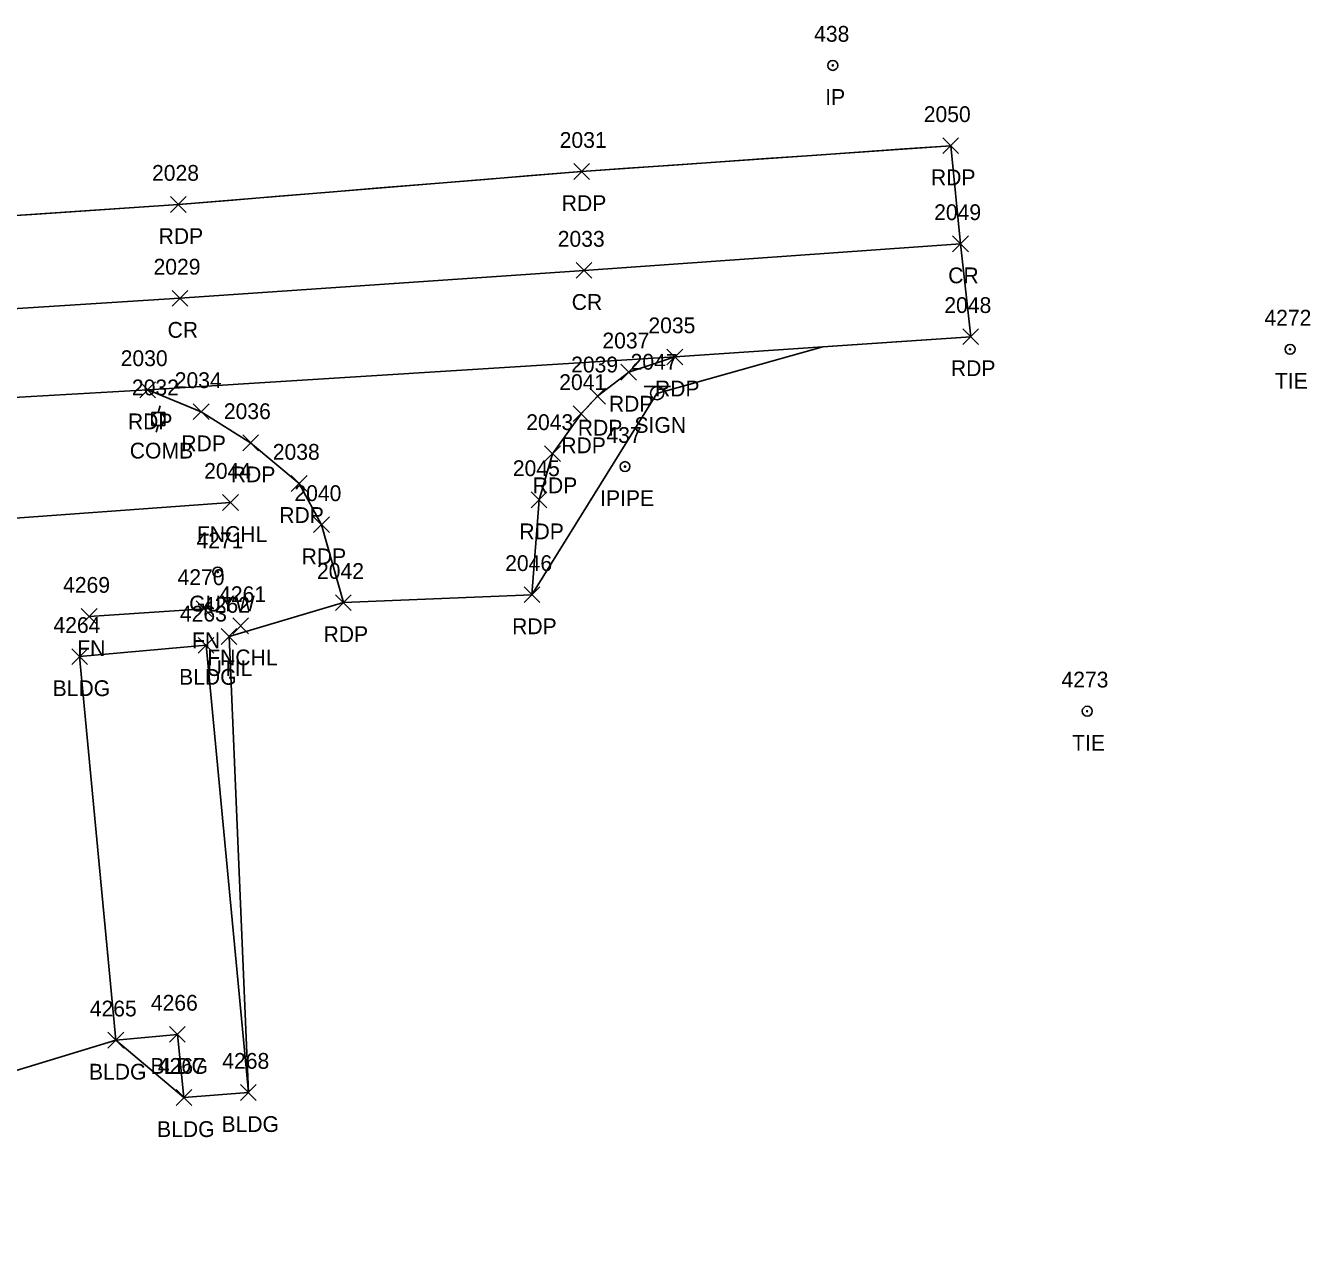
# Model space of a CAD drawing. Extents: x 1509053 to 1511576, y 400838 to 402572.
# Drawn here: x 1510951.8 to 1511114.5, y 401558.4 to 401712.6 of the extents above; entities that cross this region are included whole.
import ezdxf

# ---------------------------------------------------------------- set-up
doc = ezdxf.new("R2010")
doc.units = 0
for name, color, linetype in [('C_A', 7, 'Continuous'), ('C_I', 7, 'Continuous'), ('CBP', 7, 'Continuous'), ('L_A', 7, 'Continuous'), ('L_I', 7, 'Continuous'), ('L_TIC', 7, 'Continuous'), ('LBC', 7, 'Continuous'), ('LFNC', 7, 'Continuous'), ('LSOGP', 7, 'Continuous'), ('M_A', 7, 'Continuous'), ('M_I', 7, 'Continuous'), ('MPIP', 7, 'Continuous'), ('MPIR', 7, 'Continuous'), ('P_A', 7, 'Continuous'), ('P_I', 7, 'Continuous'), ('P_TIC', 7, 'Continuous'), ('PET', 7, 'Continuous'), ('PRC', 7, 'Continuous'), ('S_A', 7, 'Continuous'), ('S_I', 7, 'Continuous'), ('SSGN', 7, 'Continuous'), ('U_A', 7, 'Continuous'), ('U_I', 7, 'Continuous'), ('UDEFAULT', 7, 'Continuous'), ('UP', 7, 'Continuous'), ('UPGW', 7, 'Continuous')]:
    doc.layers.add(name, color=color, linetype=linetype)

msp = doc.modelspace()

# ---------------------------------------------------------------- linework, layer by layer
at = {"layer": 'CBP'}
for centre, radius in [((1511111.96, 401671.62), 0.625), ((1511111.96, 401671.62), 0.0833), ((1511086.25, 401625.79), 0.625), ((1511086.25, 401625.79), 0.0833)]:
    msp.add_circle(centre, radius, dxfattribs=at)
at = {"layer": 'L_TIC'}
for points in [[(1510976.71, 401651.22), (1510978.71, 401653.22)], [(1510978.71, 401651.22), (1510976.71, 401653.22)], [(1510973.36, 401637.76), (1510975.36, 401639.76)], [(1510975.36, 401637.76), (1510973.36, 401639.76)], [(1510958.81, 401636.78), (1510960.81, 401638.78)], [(1510960.81, 401636.78), (1510958.81, 401638.78)], [(1510978.01, 401635.6), (1510980.01, 401637.6)], [(1510980.01, 401635.6), (1510978.01, 401637.6)], [(1510973.61, 401633.14), (1510975.61, 401635.14)], [(1510975.61, 401633.14), (1510973.61, 401635.14)], [(1510957.59, 401631.7), (1510959.59, 401633.7)], [(1510959.59, 401631.7), (1510957.59, 401633.7)], [(1510969.98, 401583.86), (1510971.98, 401585.86)], [(1510971.98, 401583.86), (1510969.98, 401585.86)], [(1510962.19, 401583.13), (1510964.19, 401585.13)], [(1510964.19, 401583.13), (1510962.19, 401585.13)], [(1510970.82, 401575.86), (1510972.82, 401577.86)], [(1510972.82, 401575.86), (1510970.82, 401577.86)], [(1510978.98, 401576.5), (1510980.98, 401578.5)], [(1510980.98, 401576.5), (1510978.98, 401578.5)]]:
    msp.add_lwpolyline(points, dxfattribs=at)
at = {"layer": 'LBC'}
for points in [[(1510974.61, 401634.14), (1510958.59, 401632.7), (1510963.19, 401584.13), (1510970.98, 401584.86), (1510971.82, 401576.86), (1510979.98, 401577.5)], [(1510979.98, 401577.5), (1510974.61, 401634.14)]]:
    msp.add_lwpolyline(points, dxfattribs=at)
at = {"layer": 'LFNC'}
for points in [[(1510614.51, 401587.89), (1510608.95, 401624.6), (1510623.43, 401626.88), (1510653.12, 401627.01), (1510659.85, 401628.01), (1510675.67, 401629.95), (1510724.73, 401633.47), (1510773.82, 401637.15), (1510823.89, 401641.02), (1510977.71, 401652.22)], [(1510959.81, 401637.78), (1510974.36, 401638.76)]]:
    msp.add_lwpolyline(points, dxfattribs=at)
at = {"layer": 'LSOGP'}
msp.add_lwpolyline([(1510878.7, 401558.4), (1510963.19, 401584.13), (1510971.82, 401576.86), (1510979.98, 401577.5), (1510977.53, 401635.25), (1510992.01, 401639.54), (1511015.9, 401640.54), (1511031.74, 401666.04), (1511052.74, 401671.93), (1511062.11, 401672.57), (1511071.49, 401673.22), (1511070.2, 401684.98), (1511068.96, 401697.4), (1511063.11, 401696.99), (1511057.27, 401696.58), (1511051.42, 401696.17), (1511045.58, 401695.77), (1511039.73, 401695.36), (1511033.88, 401694.95), (1511028.04, 401694.54), (1511022.19, 401694.13), (1511015.81, 401693.61), (1511009.42, 401693.09), (1511003.03, 401692.57), (1510996.65, 401692.05), (1510990.26, 401691.52), (1510983.88, 401691), (1510977.49, 401690.48), (1510971.11, 401689.96), (1510964.93, 401689.55), (1510958.75, 401689.13), (1510952.56, 401688.71), (1510946.38, 401688.3)], dxfattribs=at)
at = {"layer": 'MPIP'}
for radius in [0.625, 0.0833]:
    msp.add_circle((1511027.7, 401656.77), radius, dxfattribs=at)
at = {"layer": 'MPIR'}
for radius in [0.625, 0.0833]:
    msp.add_circle((1511054.02, 401707.57), radius, dxfattribs=at)
at = {"layer": 'P_TIC'}
for points in [[(1511067.96, 401696.4), (1511069.96, 401698.4)], [(1511069.96, 401696.4), (1511067.96, 401698.4)], [(1511021.19, 401693.13), (1511023.19, 401695.13)], [(1511023.19, 401693.13), (1511021.19, 401695.13)], [(1510970.11, 401688.96), (1510972.11, 401690.96)], [(1510972.11, 401688.96), (1510970.11, 401690.96)], [(1511069.2, 401683.98), (1511071.2, 401685.98)], [(1511071.2, 401683.98), (1511069.2, 401685.98)], [(1511021.51, 401680.61), (1511023.51, 401682.61)], [(1511023.51, 401680.61), (1511021.51, 401682.61)], [(1510970.31, 401677.08), (1510972.31, 401679.08)], [(1510972.31, 401677.08), (1510970.31, 401679.08)], [(1511070.49, 401672.21), (1511072.49, 401674.21)], [(1511072.49, 401672.21), (1511070.49, 401674.21)], [(1511033, 401669.65), (1511035, 401671.65)], [(1511035, 401669.65), (1511033, 401671.65)], [(1511033, 401669.65), (1511035, 401671.65)], [(1511035, 401669.65), (1511033, 401671.65)], [(1511027.17, 401667.73), (1511029.17, 401669.73)], [(1511029.17, 401667.73), (1511027.17, 401669.73)], [(1510966.23, 401665.49), (1510968.23, 401667.49)], [(1510968.23, 401665.49), (1510966.23, 401667.49)], [(1510966.23, 401665.49), (1510968.23, 401667.49)], [(1510968.23, 401665.49), (1510966.23, 401667.49)], [(1511023.22, 401664.69), (1511025.22, 401666.69)], [(1511025.22, 401664.69), (1511023.22, 401666.69)], [(1510972.99, 401662.71), (1510974.99, 401664.71)], [(1510974.99, 401662.71), (1510972.99, 401664.71)], [(1511021.14, 401662.46), (1511023.13, 401664.46)], [(1511023.13, 401662.46), (1511021.14, 401664.46)], [(1510979.26, 401658.78), (1510981.26, 401660.78)], [(1510981.26, 401658.78), (1510979.26, 401660.78)], [(1511017.51, 401657.39), (1511019.51, 401659.39)], [(1511019.51, 401657.39), (1511017.51, 401659.39)], [(1510985.41, 401653.63), (1510987.41, 401655.63)], [(1510987.41, 401653.63), (1510985.41, 401655.63)], [(1511015.81, 401651.56), (1511017.81, 401653.56)], [(1511017.81, 401651.56), (1511015.81, 401653.56)], [(1510988.24, 401648.4), (1510990.24, 401650.4)], [(1510990.24, 401648.4), (1510988.24, 401650.4)], [(1511014.9, 401639.54), (1511016.9, 401641.54)], [(1511016.9, 401639.54), (1511014.9, 401641.54)], [(1510991.01, 401638.54), (1510993.01, 401640.54)], [(1510993.01, 401638.54), (1510991.01, 401640.54)]]:
    msp.add_lwpolyline(points, dxfattribs=at)
at = {"layer": 'PET'}
for points in [[(1510621.58, 401670.53), (1510656.11, 401672.66), (1510671.73, 401673.2), (1510721.32, 401677.33), (1510730.99, 401677.85), (1510771.86, 401678.86), (1510821.69, 401680.89), (1510871.79, 401683.93), (1510921.66, 401686.63), (1510971.11, 401689.96), (1511022.19, 401694.13), (1511068.96, 401697.4)], [(1510069.7, 401647.38), (1510070.82, 401637.95), (1510072.41, 401628.04), (1510122.3, 401634.81), (1510170.19, 401640.65), (1510220.23, 401643.86), (1510269.72, 401644.29), (1510320.63, 401641.42), (1510370.24, 401637.87), (1510421.73, 401637.03), (1510472.3, 401638.25), (1510523.24, 401640.81), (1510571.7, 401643.53), (1510622.45, 401646.41), (1510672.72, 401649.13), (1510722.86, 401651.91), (1510723.41, 401651.94), (1510773.15, 401654.37), (1510822.4, 401657.74), (1510872.35, 401660.8), (1510922.85, 401663.95), (1510967.23, 401666.49), (1511034, 401670.65), (1511071.49, 401673.22)], [(1511034, 401670.65), (1511028.17, 401668.73), (1511024.22, 401665.69), (1511022.14, 401663.46), (1511018.51, 401658.39), (1511016.81, 401652.56), (1511015.9, 401640.54)], [(1510967.23, 401666.49), (1510973.99, 401663.71), (1510980.26, 401659.78), (1510986.41, 401654.63), (1510989.24, 401649.4), (1510992.01, 401639.54)]]:
    msp.add_lwpolyline(points, dxfattribs=at)
at = {"layer": 'PRC'}
msp.add_lwpolyline([(1510070.82, 401637.95), (1510120.23, 401645.42), (1510169.76, 401652.13), (1510220.07, 401655.52), (1510220.14, 401655.43), (1510270.51, 401655.53), (1510320.84, 401653.34), (1510371.03, 401650.53), (1510421.26, 401649.11), (1510471.33, 401650.1), (1510521.34, 401652.38), (1510571.58, 401655.12), (1510621.67, 401657.75), (1510671.66, 401660.66), (1510722.15, 401663.46), (1510772.15, 401666.42), (1510822.28, 401669.1), (1510872.26, 401671.98), (1510872.29, 401672.01), (1510922.21, 401674.96), (1510971.31, 401678.08), (1511022.51, 401681.61), (1511070.2, 401684.98)], dxfattribs=at)
at = {"layer": 'SSGN'}
for p, q in [((1511030.11, 401666.9), (1511033.44, 401666.9)), ((1511031.76, 401666.06), (1511031.76, 401666.06))]:
    msp.add_line(p, q, dxfattribs=at)
msp.add_circle((1511031.76, 401666.06), 0.833, dxfattribs=at)
at = {"layer": 'UDEFAULT'}
for points in [[(1510976.53, 401634.25), (1510978.53, 401636.25)], [(1510978.53, 401634.25), (1510976.53, 401636.25)]]:
    msp.add_lwpolyline(points, dxfattribs=at)
at = {"layer": 'UP'}
for p, q in [((1510967.73, 401661.96), (1510967.73, 401663.62)), ((1510967.73, 401663.62), (1510969.39, 401663.62)), ((1510968.81, 401664.46), (1510968.56, 401663.62)), ((1510969.39, 401663.62), (1510969.39, 401661.96)), ((1510969.39, 401661.96), (1510967.73, 401661.96)), ((1510968.31, 401661.12), (1510968.56, 401661.96)), ((1510968.56, 401662.79), (1510968.56, 401662.79))]:
    msp.add_line(p, q, dxfattribs=at)
msp.add_circle((1510968.56, 401662.79), 0.833, dxfattribs=at)
at = {"layer": 'UPGW'}
for radius in [0.625, 0.0833]:
    msp.add_circle((1510976.09, 401643.42), radius, dxfattribs=at)

# ---------------------------------------------------------------- texts
at = {"layer": 'C_A'}
for p in [(1511110.04, 401666.62), (1511084.33, 401620.79)]:
    msp.add_text('TIE', height=2, dxfattribs=at).set_placement(p)
at = {"layer": 'C_I'}
for s, p in [('4272', (1511108.7, 401674.62)), ('4273', (1511082.99, 401628.79))]:
    msp.add_text(s, height=2, dxfattribs=at).set_placement(p)
at = {"layer": 'L_A'}
for s, p in [('FNCHL', (1510973.45, 401647.22)), ('FN', (1510972.84, 401633.76)), ('FN', (1510958.29, 401632.78)), ('FNCHL', (1510974.76, 401631.6)), ('BLDG', (1510971.2, 401629.14)), ('BLDG', (1510955.18, 401627.7)), ('BLDG', (1510959.78, 401579.13)), ('BLDG', (1510967.57, 401579.86)), ('BLDG', (1510968.41, 401571.86)), ('BLDG', (1510976.57, 401572.5))]:
    msp.add_text(s, height=2, dxfattribs=at).set_placement(p)
at = {"layer": 'L_I'}
for s, p in [('2044', (1510974.37, 401655.22)), ('4269', (1510956.5, 401640.78)), ('4270', (1510971.01, 401641.76)), ('4261', (1510976.27, 401639.6)), ('4263', (1510971.3, 401637.14)), ('4264', (1510955.28, 401635.7)), ('4265', (1510959.88, 401587.13)), ('4266', (1510967.62, 401587.86)), ('4268', (1510976.67, 401580.5)), ('4267', (1510968.51, 401579.86))]:
    msp.add_text(s, height=2, dxfattribs=at).set_placement(p)
at = {"layer": 'M_A'}
for s, p in [('IP', (1511053.06, 401702.57)), ('IPIPE', (1511024.54, 401651.77))]:
    msp.add_text(s, height=2, dxfattribs=at).set_placement(p)
at = {"layer": 'M_I'}
for s, p in [('438', (1511051.65, 401710.57)), ('437', (1511025.34, 401659.77))]:
    msp.add_text(s, height=2, dxfattribs=at).set_placement(p)
at = {"layer": 'P_A'}
for s, p in [('RDP', (1511066.45, 401692.4)), ('RDP', (1511019.68, 401689.13)), ('RDP', (1510968.6, 401684.96)), ('CR', (1511068.64, 401679.98)), ('CR', (1511020.94, 401676.61)), ('CR', (1510969.74, 401673.08)), ('RDP', (1511068.98, 401668.22)), ('RDP', (1511031.49, 401665.65)), ('RDP', (1511031.49, 401665.65)), ('RDP', (1511025.65, 401663.73)), ('RDP', (1510964.71, 401661.49)), ('RDP', (1510964.71, 401661.49)), ('RDP', (1511021.71, 401660.69)), ('RDP', (1510971.48, 401658.71)), ('RDP', (1511019.62, 401658.46)), ('RDP', (1510977.75, 401654.78)), ('RDP', (1511016, 401653.39)), ('RDP', (1510983.89, 401649.63)), ('RDP', (1511014.3, 401647.56)), ('RDP', (1510986.72, 401644.4)), ('RDP', (1511013.39, 401635.54)), ('RDP', (1510989.5, 401634.54))]:
    msp.add_text(s, height=2, dxfattribs=at).set_placement(p)
at = {"layer": 'P_I'}
for s, p in [('2050', (1511065.54, 401700.4)), ('2031', (1511019.42, 401697.13)), ('2028', (1510967.77, 401692.96)), ('2049', (1511066.86, 401687.98)), ('2033', (1511019.17, 401684.61)), ('2029', (1510967.96, 401681.08)), ('2048', (1511068.15, 401676.22)), ('2035', (1511030.66, 401673.65)), ('2035', (1511030.66, 401673.65)), ('2037', (1511024.83, 401671.73)), ('2030', (1510963.8, 401669.49)), ('2030', (1510963.8, 401669.49)), ('2039', (1511020.87, 401668.69)), ('2034', (1510970.65, 401666.71)), ('2041', (1511019.36, 401666.46)), ('2036', (1510976.87, 401662.78)), ('2043', (1511015.18, 401661.39)), ('2038', (1510983.07, 401657.63)), ('2045', (1511013.48, 401655.56)), ('2040', (1510985.81, 401652.4)), ('2046', (1511012.51, 401643.54)), ('2042', (1510988.67, 401642.54))]:
    msp.add_text(s, height=2, dxfattribs=at).set_placement(p)
at = {"layer": 'S_A'}
msp.add_text('SIGN', height=2, dxfattribs=at).set_placement((1511028.89, 401661.04))
at = {"layer": 'S_I'}
msp.add_text('2047', height=2, dxfattribs=at).set_placement((1511028.4, 401669.04))
at = {"layer": 'U_A'}
for s, p in [('COMB', (1510964.95, 401657.79)), ('GUYW', (1510972.48, 401638.42)), ('UTIL', (1510974.7, 401630.25))]:
    msp.add_text(s, height=2, dxfattribs=at).set_placement(p)
at = {"layer": 'U_I'}
for s, p in [('2032', (1510965.22, 401665.79)), ('4271', (1510973.4, 401646.42)), ('4262', (1510974.22, 401638.25))]:
    msp.add_text(s, height=2, dxfattribs=at).set_placement(p)

doc.saveas('drawing.dxf')
